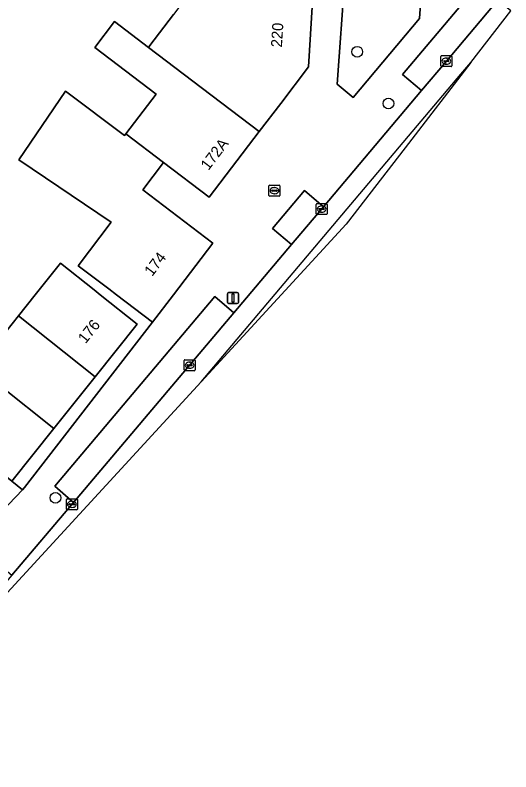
# Model space of a CAD drawing. Extents: x 160102 to 160934, y 382045 to 382923.
# Drawn here: x 160501.4 to 160546.5, y 382206.7 to 382275.4 of the extents above; entities that cross this region are included whole.
import ezdxf

# ---------------------------------------------------------------- set-up
doc = ezdxf.new("R2010")
doc.units = 0
for name, color, linetype in [('IMGEO_Boom', 7, 'Continuous'), ('IMGEO_Brandkraan', 7, 'Continuous'), ('IMGEO_Erf', 7, 'Continuous'), ('IMGEO_Groenvoorziening', 7, 'Continuous'), ('IMGEO_Kolk', 7, 'Continuous'), ('IMGEO_Lichtmast', 7, 'Continuous'), ('IMGEO_Pand', 7, 'Continuous'), ('IMGEO_Pand_nummerreeks', 7, 'Continuous'), ('IMGEO_Parkeervlak_open', 7, 'Continuous'), ('IMGEO_Rijbaan_lokaal_gesloten', 7, 'Continuous'), ('IMGEO_Rijbaan_lokaal_open', 7, 'Continuous'), ('IMGEO_Voetpad_open', 7, 'Continuous')]:
    doc.layers.add(name, color=color, linetype=linetype)

msp = doc.modelspace()

# ---------------------------------------------------------------- linework, layer by layer
at = {"layer": 'IMGEO_Boom'}
for centre in [(160532.528, 382272.084), (160535.367, 382267.384), (160505.11, 382231.563)]:
    msp.add_circle(centre, 0.489, dxfattribs=at)
at = {"layer": 'IMGEO_Brandkraan'}
for p, q in [((160524.508, 382259.041), (160524.508, 382259.893)), ((160524.583, 382259.967), (160525.435, 382259.967)), ((160524.996, 382259.747), (160525.021, 382259.747)), ((160525.509, 382259.893), (160525.509, 382259.041)), ((160525.435, 382258.967), (160524.583, 382258.967)), ((160524.767, 382259.461), (160524.767, 382259.473)), ((160525.205, 382259.424), (160524.807, 382259.424)), ((160524.81, 382259.51), (160525.208, 382259.51)), ((160525.019, 382259.187), (160524.994, 382259.187)), ((160525.251, 382259.473), (160525.251, 382259.461))]:
    msp.add_line(p, q, dxfattribs=at)
for points in [[(160524.508, 382259.041), (160524.508, 382259.893)], [(160524.583, 382259.967), (160525.435, 382259.967)], [(160525.509, 382259.893), (160525.509, 382259.041)], [(160525.435, 382258.967), (160524.583, 382258.967)]]:
    msp.add_lwpolyline(points, dxfattribs=at)
for centre, radius, start, end in [((160524.585, 382259.891), 0.0765, 91.55205, 178.44795), ((160524.585, 382259.891), 0.0765, 91.55205, 178.44795), ((160525.433, 382259.891), 0.0765, 1.55205, 88.44795), ((160525.433, 382259.891), 0.0765, 1.55205, 88.44795), ((160524.585, 382259.043), 0.0765, 181.55205, 268.44795), ((160524.585, 382259.043), 0.0765, 181.55205, 268.44795), ((160524.807, 382259.47), 0.0403, 85.87752, 175.75265), ((160524.804, 382259.46), 0.0366, 178.93798, 274.71019), ((160525.208, 382259.467), 0.043, 264.86636, 352.45326), ((160525.212, 382259.472), 0.0386, 1.73085, 96.63898), ((160525.433, 382259.043), 0.0765, 271.55205, 358.44795), ((160525.433, 382259.043), 0.0765, 271.55205, 358.44795)]:
    msp.add_arc(centre, radius, start, end, dxfattribs=at)
for centre, major_axis, ratio, start_param, end_param in [((160524.995, 382259.467), (-0.387, 0.002), 0.722429, 4.712389, 7.853982), ((160525.02, 382259.467), (-0.39, 0.002), 0.717154, 1.570796, 4.712389)]:
    msp.add_ellipse(centre, major_axis=major_axis, ratio=ratio, start_param=start_param, end_param=end_param, dxfattribs=at)
at = {"layer": 'IMGEO_Erf'}
msp.add_lwpolyline([(160500, 382245.927), (160501.743, 382248.096), (160503.272, 382250), (160505.58, 382252.873), (160508.617, 382250.452), (160509.184, 382250), (160512.526, 382247.336), (160508.707, 382242.545), (160504.964, 382237.85), (160501.148, 382233.064), (160502.108, 382232.289), (160502.304, 382232.493), (160513.942, 382247.516), (160510.67, 382250), (160509.96, 382250.539), (160507.174, 382252.653), (160510.174, 382256.594), (160501.775, 382262.269), (160506.007, 382268.51), (160511.392, 382264.478), (160511.504, 382264.625), (160514.257, 382268.241), (160508.685, 382272.482), (160510.478, 382274.837), (160513.573, 382272.48), (160513.7, 382272.646), (160515.841, 382275.457)], dxfattribs=at)
at = {"layer": 'IMGEO_Groenvoorziening'}
msp.add_lwpolyline([(160539.326, 382291.951), (160535.051, 382292.23), (160532.114, 382288.433), (160530.695, 382269.144), (160532.176, 382267.939), (160538.203, 382275.097)], close=True, dxfattribs=at)
at = {"layer": 'IMGEO_Kolk'}
for p, q in [((160540.127, 382270.808), (160540.127, 382271.66)), ((160540.202, 382271.734), (160541.054, 382271.734)), ((160540.615, 382271.514), (160540.64, 382271.514)), ((160541.128, 382271.66), (160541.128, 382270.808)), ((160541.054, 382270.734), (160540.202, 382270.734)), ((160540.386, 382271.228), (160540.386, 382271.24)), ((160540.824, 382271.191), (160540.426, 382271.191)), ((160540.429, 382271.277), (160540.827, 382271.277)), ((160540.638, 382270.954), (160540.613, 382270.954)), ((160540.87, 382271.24), (160540.87, 382271.228)), ((160528.873, 382258.297), (160529.725, 382258.297)), ((160528.798, 382257.371), (160528.798, 382258.223)), ((160529.057, 382257.791), (160529.057, 382257.803)), ((160529.495, 382257.754), (160529.097, 382257.754)), ((160529.1, 382257.84), (160529.498, 382257.84)), ((160529.286, 382258.077), (160529.311, 382258.077)), ((160529.541, 382257.803), (160529.541, 382257.791)), ((160529.799, 382258.223), (160529.799, 382257.371)), ((160529.725, 382257.297), (160528.873, 382257.297)), ((160529.309, 382257.517), (160529.284, 382257.517)), ((160516.8, 382243.18), (160516.8, 382244.032)), ((160516.875, 382244.106), (160517.727, 382244.106)), ((160517.288, 382243.886), (160517.313, 382243.886)), ((160517.801, 382244.032), (160517.801, 382243.18)), ((160517.727, 382243.106), (160516.875, 382243.106)), ((160517.059, 382243.6), (160517.059, 382243.612)), ((160517.497, 382243.563), (160517.099, 382243.563)), ((160517.102, 382243.649), (160517.5, 382243.649)), ((160517.311, 382243.326), (160517.286, 382243.326)), ((160517.543, 382243.612), (160517.543, 382243.6)), ((160506.176, 382231.471), (160507.028, 382231.471)), ((160506.101, 382230.545), (160506.101, 382231.397)), ((160506.36, 382230.965), (160506.36, 382230.977)), ((160506.798, 382230.928), (160506.4, 382230.928)), ((160506.403, 382231.014), (160506.801, 382231.014)), ((160506.589, 382231.251), (160506.614, 382231.251)), ((160506.844, 382230.977), (160506.844, 382230.965)), ((160507.102, 382231.397), (160507.102, 382230.545)), ((160507.028, 382230.471), (160506.176, 382230.471)), ((160506.612, 382230.691), (160506.587, 382230.691))]:
    msp.add_line(p, q, dxfattribs=at)
for points in [[(160540.127, 382270.808), (160540.127, 382271.66)], [(160540.202, 382271.734), (160541.054, 382271.734)], [(160541.128, 382271.66), (160541.128, 382270.808)], [(160541.054, 382270.734), (160540.202, 382270.734)], [(160528.873, 382258.297), (160529.725, 382258.297)], [(160528.798, 382257.371), (160528.798, 382258.223)], [(160529.799, 382258.223), (160529.799, 382257.371)], [(160529.725, 382257.297), (160528.873, 382257.297)], [(160516.8, 382243.18), (160516.8, 382244.032)], [(160516.875, 382244.106), (160517.727, 382244.106)], [(160517.801, 382244.032), (160517.801, 382243.18)], [(160517.727, 382243.106), (160516.875, 382243.106)], [(160506.176, 382231.471), (160507.028, 382231.471)], [(160506.101, 382230.545), (160506.101, 382231.397)], [(160507.102, 382231.397), (160507.102, 382230.545)], [(160507.028, 382230.471), (160506.176, 382230.471)]]:
    msp.add_lwpolyline(points, dxfattribs=at)
for centre, radius, start, end in [((160540.204, 382271.658), 0.0765, 91.55205, 178.44795), ((160540.204, 382271.658), 0.0765, 91.55205, 178.44795), ((160541.052, 382271.658), 0.0765, 1.55205, 88.44795), ((160541.052, 382271.658), 0.0765, 1.55205, 88.44795), ((160540.204, 382270.81), 0.0765, 181.55205, 268.44795), ((160540.204, 382270.81), 0.0765, 181.55205, 268.44795), ((160540.426, 382271.237), 0.0403, 85.87752, 175.75265), ((160540.423, 382271.227), 0.0366, 178.93798, 274.71019), ((160540.827, 382271.234), 0.043, 264.86636, 352.45326), ((160540.831, 382271.239), 0.0386, 1.73085, 96.63898), ((160541.052, 382270.81), 0.0765, 271.55205, 358.44795), ((160541.052, 382270.81), 0.0765, 271.55205, 358.44795), ((160528.875, 382258.221), 0.0765, 91.55205, 178.44795), ((160528.875, 382258.221), 0.0765, 91.55205, 178.44795), ((160529.723, 382258.221), 0.0765, 1.55205, 88.44795), ((160529.723, 382258.221), 0.0765, 1.55205, 88.44795), ((160529.097, 382257.8), 0.0403, 85.87752, 175.75265), ((160529.094, 382257.79), 0.0366, 178.93798, 274.71019), ((160529.498, 382257.797), 0.043, 264.86636, 352.45326), ((160529.502, 382257.802), 0.0386, 1.73085, 96.63898), ((160528.875, 382257.373), 0.0765, 181.55205, 268.44795), ((160528.875, 382257.373), 0.0765, 181.55205, 268.44795), ((160529.723, 382257.373), 0.0765, 271.55205, 358.44795), ((160529.723, 382257.373), 0.0765, 271.55205, 358.44795), ((160516.877, 382244.03), 0.0765, 91.55205, 178.44795), ((160516.877, 382244.03), 0.0765, 91.55205, 178.44795), ((160517.725, 382244.03), 0.0765, 1.55205, 88.44795), ((160517.725, 382244.03), 0.0765, 1.55205, 88.44795), ((160516.877, 382243.182), 0.0765, 181.55205, 268.44795), ((160516.877, 382243.182), 0.0765, 181.55205, 268.44795), ((160517.099, 382243.609), 0.0403, 85.87752, 175.75265), ((160517.096, 382243.599), 0.0366, 178.93798, 274.71019), ((160517.5, 382243.606), 0.043, 264.86636, 352.45326), ((160517.504, 382243.611), 0.0386, 1.73085, 96.63898), ((160517.725, 382243.182), 0.0765, 271.55205, 358.44795), ((160517.725, 382243.182), 0.0765, 271.55205, 358.44795), ((160506.178, 382231.395), 0.0765, 91.55205, 178.44795), ((160506.178, 382231.395), 0.0765, 91.55205, 178.44795), ((160507.026, 382231.395), 0.0765, 1.55205, 88.44795), ((160507.026, 382231.395), 0.0765, 1.55205, 88.44795), ((160506.4, 382230.974), 0.0403, 85.87752, 175.75265), ((160506.397, 382230.964), 0.0366, 178.93798, 274.71019), ((160506.801, 382230.971), 0.043, 264.86636, 352.45326), ((160506.805, 382230.976), 0.0386, 1.73085, 96.63898), ((160506.178, 382230.547), 0.0765, 181.55205, 268.44795), ((160506.178, 382230.547), 0.0765, 181.55205, 268.44795), ((160507.026, 382230.547), 0.0765, 271.55205, 358.44795), ((160507.026, 382230.547), 0.0765, 271.55205, 358.44795)]:
    msp.add_arc(centre, radius, start, end, dxfattribs=at)
for centre, major_axis, ratio, start_param, end_param in [((160540.614, 382271.234), (-0.387, 0.002), 0.722429, 4.712389, 7.853982), ((160540.639, 382271.234), (-0.39, 0.002), 0.717154, 1.570796, 4.712389), ((160529.285, 382257.797), (-0.387, 0.002), 0.722429, 4.712389, 7.853982), ((160529.31, 382257.797), (-0.39, 0.002), 0.717154, 1.570796, 4.712389), ((160517.287, 382243.606), (-0.387, 0.002), 0.722429, 4.712389, 7.853982), ((160517.312, 382243.606), (-0.39, 0.002), 0.717154, 1.570796, 4.712389), ((160506.588, 382230.971), (-0.387, 0.002), 0.722429, 4.712389, 7.853982), ((160506.613, 382230.971), (-0.39, 0.002), 0.717154, 1.570796, 4.712389)]:
    msp.add_ellipse(centre, major_axis=major_axis, ratio=ratio, start_param=start_param, end_param=end_param, dxfattribs=at)
at = {"layer": 'IMGEO_Lichtmast'}
for p, q in [((160520.74, 382249.307), (160520.74, 382250.107)), ((160520.74, 382250.107), (160520.74, 382249.307)), ((160520.84, 382250.207), (160521.63, 382250.207)), ((160521.63, 382250.207), (160520.84, 382250.207)), ((160521.73, 382250.107), (160521.73, 382249.307)), ((160521.73, 382249.307), (160521.73, 382250.107)), ((160521.63, 382249.207), (160520.84, 382249.207)), ((160520.84, 382249.207), (160521.63, 382249.207))]:
    msp.add_line(p, q, dxfattribs=at)
msp.add_lwpolyline([(160521.16, 382250.082), (160521.31, 382250.082), (160521.31, 382249.332), (160521.16, 382249.332), (160521.16, 382250.082)], dxfattribs=at)
for centre, start, end in [((160520.84, 382250.107), 90, 180), ((160520.84, 382250.107), 90, 180), ((160521.63, 382250.107), 0, 90), ((160521.63, 382250.107), 360, 90), ((160520.84, 382249.307), 180, 270), ((160520.84, 382249.307), 180, 270), ((160521.63, 382249.307), 270, 0), ((160521.63, 382249.307), 270, 0)]:
    msp.add_arc(centre, 0.1, start, end, dxfattribs=at)
at = {"layer": 'IMGEO_Pand'}
for points in [[(160528.47, 382276.649), (160518.036, 382277.256), (160517.13, 382277.23), (160515.841, 382275.457), (160513.7, 382272.646), (160513.573, 382272.48), (160517.595, 382269.417), (160523.621, 382264.828), (160525.574, 382267.393), (160528.099, 382270.71)], [(160517.595, 382269.417), (160513.573, 382272.48), (160510.478, 382274.837), (160508.685, 382272.482), (160514.257, 382268.241), (160511.504, 382264.625), (160514.932, 382262.021), (160519.08, 382258.864), (160523.621, 382264.828)], [(160514.932, 382262.021), (160511.504, 382264.625), (160511.392, 382264.478), (160506.007, 382268.51), (160501.775, 382262.269), (160510.174, 382256.594), (160507.174, 382252.653), (160509.96, 382250.539), (160510.67, 382250), (160513.942, 382247.516), (160515.831, 382250), (160519.411, 382254.709), (160513.051, 382259.55)], [(160501.743, 382248.096), (160508.707, 382242.545), (160512.526, 382247.336), (160509.184, 382250), (160508.617, 382250.452), (160505.58, 382252.873), (160503.272, 382250)], [(160504.964, 382237.85), (160508.707, 382242.545), (160501.743, 382248.096), (160500, 382245.927), (160497.982, 382243.416), (160500, 382241.807)], [(160504.964, 382237.85), (160500, 382241.807), (160497.982, 382243.416), (160497.273, 382242.533), (160494.111, 382238.659), (160500, 382233.977), (160501.148, 382233.064)]]:
    msp.add_lwpolyline(points, close=True, dxfattribs=at)
at = {"layer": 'IMGEO_Parkeervlak_open'}
for points in [[(160545.302, 382276.788), (160545.686, 382277.242), (160546.492, 382278.195), (160546.224, 382278.419), (160544.765, 382279.636), (160536.643, 382270.017), (160538.372, 382268.558), (160540.628, 382271.234)], [(160529.474, 382258.004), (160527.741, 382259.47), (160524.839, 382256.034), (160526.566, 382254.565)], [(160521.326, 382248.366), (160519.591, 382249.85), (160505.04, 382232.613), (160506.753, 382231.15)]]:
    msp.add_lwpolyline(points, close=True, dxfattribs=at)
at = {"layer": 'IMGEO_Rijbaan_lokaal_gesloten'}
msp.add_lwpolyline([(160546.482, 382275.816), (160545.302, 382276.788), (160540.628, 382271.234), (160538.372, 382268.558), (160529.474, 382258.004), (160526.566, 382254.565), (160521.326, 382248.366), (160506.753, 382231.15), (160501.147, 382224.522), (160492.804, 382214.635), (160490.686, 382212.102), (160490.012, 382211.302), (160518.337, 382242.093), (160541.957, 382270.046), (160542.854, 382271.114), (160546.482, 382275.816)], dxfattribs=at)
at = {"layer": 'IMGEO_Rijbaan_lokaal_open'}
msp.add_lwpolyline([(160542.854, 382271.114), (160536.882, 382263.373), (160531.527, 382256.432), (160518.337, 382242.093), (160541.957, 382270.046), (160542.854, 382271.114)], dxfattribs=at)
msp.add_lwpolyline([(160488.015, 382245.58), (160483.572, 382250), (160477.907, 382255.636), (160475.718, 382257.796), (160475.219, 382258.289), (160472.924, 382259.712), (160472.455, 382258.979), (160469.704, 382254.68), (160469.844, 382254.548), (160471.412, 382253.166), (160472.898, 382251.857), (160473.904, 382250.928), (160474.909, 382250), (160477.82, 382247.311), (160491.712, 382233.348), (160497.684, 382227.685), (160502.108, 382232.289), (160501.148, 382233.064), (160500, 382233.977), (160494.111, 382238.659), (160488.226, 382243.35)], close=True, dxfattribs=at)
at = {"layer": 'IMGEO_Voetpad_open'}
msp.add_lwpolyline([(160532.114, 382288.433), (160535.051, 382292.23), (160539.326, 382291.951), (160538.203, 382275.097), (160532.176, 382267.939), (160530.695, 382269.144)], close=True, dxfattribs=at)
for points in [[(160486.596, 382207.589), (160485.025, 382208.957), (160488.954, 382213.566), (160490.686, 382212.102), (160492.804, 382214.635), (160491.083, 382216.121), (160499.438, 382225.958), (160501.147, 382224.522), (160506.753, 382231.15), (160505.04, 382232.613), (160519.591, 382249.85), (160521.326, 382248.366), (160526.566, 382254.565), (160524.839, 382256.034), (160527.741, 382259.47), (160529.474, 382258.004), (160538.372, 382268.558), (160536.643, 382270.017), (160544.765, 382279.636), (160546.224, 382278.419)], [(160528.47, 382276.649), (160528.099, 382270.71), (160525.574, 382267.393), (160523.621, 382264.828), (160519.08, 382258.864), (160514.932, 382262.021), (160513.051, 382259.55), (160519.411, 382254.709), (160515.831, 382250), (160513.942, 382247.516), (160502.304, 382232.493), (160502.108, 382232.289), (160497.684, 382227.685), (160493.693, 382223.469), (160491.942, 382221.619), (160486.148, 382215.5), (160485.952, 382215.293), (160486.999, 382214.3), (160482.011, 382209.035), (160480.965, 382210.025), (160479.982, 382208.986), (160478.508, 382207.36), (160470.549, 382198.506)]]:
    msp.add_lwpolyline(points, dxfattribs=at)

# ---------------------------------------------------------------- texts
at = {"layer": 'IMGEO_Pand_nummerreeks'}
for s, rotation, p in [('220', 86.42495, (160525.684, 382272.464)), ('172A', 52.71212, (160519.009, 382261.247)), ('174', 52.75345, (160513.891, 382251.614)), ('176', 51.44096, (160507.843, 382245.505))]:
    msp.add_text(s, height=1, rotation=rotation, dxfattribs=at).set_placement(p)

doc.saveas('drawing.dxf')
